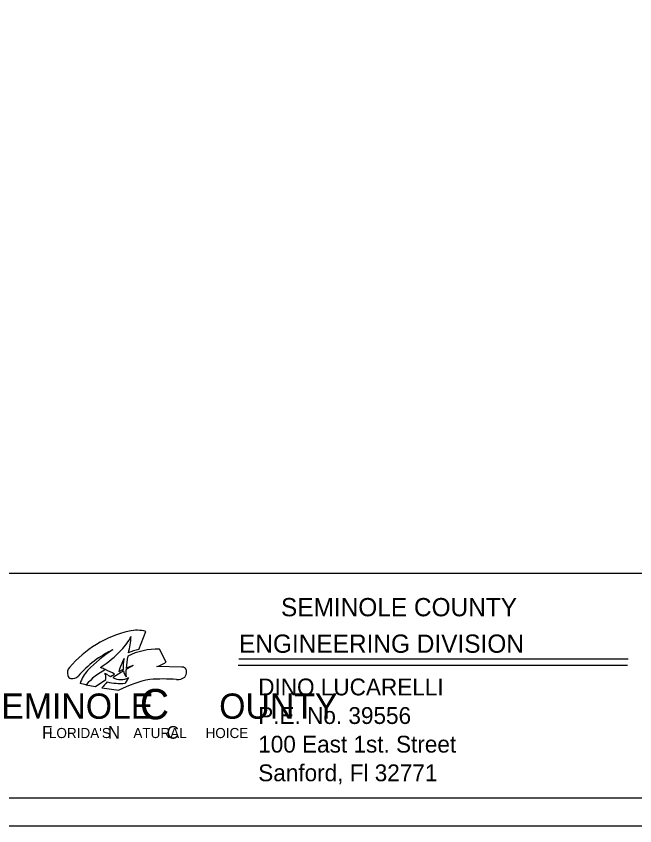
# Model space of a CAD drawing. Extents: x 539344 to 540004, y 1574686 to 1575110.
# Drawn here: x 539600.9 to 539689, y 1574686.5 to 1574801.8 of the extents above; entities that cross this region are included whole.
import ezdxf

# ---------------------------------------------------------------- set-up
doc = ezdxf.new("R2010")
doc.units = 0
for name, color, linetype in [('Logo_dp', 7, 'Continuous'), ('PlotBorder_dp', 7, 'Continuous'), ('SheetBorder_dp', 7, 'Continuous'), ('TextMisc', 7, 'Continuous')]:
    doc.layers.add(name, color=color, linetype=linetype)

msp = doc.modelspace()

# ---------------------------------------------------------------- linework, layer by layer
at = {"layer": 'Logo_dp'}
for p, q in [((539618.37, 1574711.59), (539619.39, 1574714.15)), ((539622.26, 1574709.78), (539621.31, 1574711.62)), ((539624.5, 1574709.07), (539620.95, 1574709.15)), ((539614.36, 1574707.7), (539614.93, 1574708.05)), ((539612.21, 1574706.28), (539613.68, 1574707.27)), ((539613.68, 1574707.27), (539613.68, 1574707.85)), ((539616.92, 1574707.57), (539616.42, 1574706.76)), ((539610.85, 1574706.54), (539612.21, 1574706.28)), ((539613.13, 1574706.1), (539615.54, 1574705.76))]:
    msp.add_line(p, q, dxfattribs=at)
for points in [[(539617.02, 1574714.19), (539617.02, 1574714.19)], [(539611.09, 1574708.58), (539611.09, 1574708.58)]]:
    msp.add_lwpolyline(points, dxfattribs=at)
for centre, radius, start, end in [((539620.59, 1574698.7), 15.89, 102.9903, 139.6059), ((539618.13, 1574709.35), 4.96, 75.3253, 102.9903), ((539610.89, 1574716.45), 7.05, 315.4846, 334.5843), ((539608.31, 1574713.66), 8.96, 343.2724, 358.4983), ((539620.79, 1574698.34), 14.53, 114.9659, 139.5324), ((539624.77, 1574695.63), 18.84, 122.4911, 136.5671), ((539601.1, 1574726.09), 20.79, 304.6341, 315.4846), ((539621.11, 1574701.89), 9.74, 88.8097, 116.3253), ((539619.98, 1574704.41), 7.35, 102.6743, 114.927), ((539622.26, 1574706.8), 6.91, 149.8559, 166.6084), ((539620.31, 1574709.17), 4.17, 164.7271, 186.2913), ((539629.12, 1574708.11), 12.58, 168.5397, 176.4368), ((539629.51, 1574685.9), 26.24, 117.0216, 119.5789), ((539621.65, 1574696.98), 12.96, 108.2919, 113.1245), ((539619.53, 1574713.79), 4.86, 286.9862, 304.2368), ((539624.53, 1574708.43), 0.643, 0.9885, 92.5741), ((539609.42, 1574708.21), 1.22, 139.6059, 196.4516), ((539614.46, 1574705.39), 4.64, 136.5671, 163.5792), ((539618, 1574700.23), 9.53, 117.2749, 138.5612), ((539618, 1574700.23), 9.53, 117.2749, 138.5612), ((539611.87, 1574705.19), 3.93, 63.4009, 74.6531), ((539613.08, 1574707.75), 0.608, 9.3089, 39.4038), ((539613.28, 1574707.02), 1.15, 52.8844, 76.2699), ((539607.58, 1574695.02), 14.96, 60.5981, 66.1485), ((539615.16, 1574709.45), 1.93, 231.8585, 245.4301), ((539629.51, 1574685.9), 26.24, 120.5054, 124.3665), ((539621.65, 1574696.98), 12.96, 115.0847, 118.1751), ((539617.71, 1574708.72), 1.54, 187.6078, 223.6575), ((539629.12, 1574708.11), 12.58, 177.2074, 179.7242), ((539618.24, 1574708.11), 1.71, 177.7479, 195.3391), ((539624.1, 1574708.33), 1.07, 319.3898, 5.6197), ((539608.82, 1574708.03), 0.599, 196.4516, 259.2243), ((539608.92, 1574708.55), 1.12, 259.2243, 316.3038), ((539624.04, 1574697.34), 13.99, 136.6419, 141.2542), ((539615.74, 1574714.82), 8.09, 256.604, 274.8219), ((539615.8, 1574709.7), 2.41, 242.5498, 297.6527), ((539622.82, 1574691.88), 15.68, 100.5294, 117.6775), ((539621.85, 1574686.34), 21.03, 84.8254, 95.1746), ((539623.93, 1574708.81), 1.53, 262.9671, 309.9257), ((539606.9, 1574688.08), 18.88, 77.906, 80.5112)]:
    msp.add_arc(centre, radius, start, end, dxfattribs=at)
at = {"layer": 'PlotBorder_dp'}
msp.add_lwpolyline([(539343.95, 1574686.45), (540003.95, 1574686.45), (540003.95, 1575110.45), (539343.95, 1575110.45)], close=True, dxfattribs=at)
at = {"layer": 'SheetBorder_dp'}
for p, q in [((539365.95, 1574722.45), (539981.95, 1574722.45)), ((539365.95, 1574690.45), (539981.95, 1574690.45))]:
    msp.add_line(p, q, dxfattribs=at)
at = {"layer": 'TextMisc'}
for p, q in [((539632.6, 1574710.24), (539688.06, 1574710.24)), ((539632.52, 1574709.34), (539687.98, 1574709.34))]:
    msp.add_line(p, q, dxfattribs=at)

# ---------------------------------------------------------------- texts
at = {"layer": 'Logo_dp'}
for s, height, p in [('C', 4.32, (539618.52, 1574701.62)), ('EMINOLE       OUNTY', 3.6, (539598.79, 1574701.7)), ('F', 1.8, (539604.6, 1574698.86)), ("LORIDA'S      ATURAL     HOICE", 1.44, (539605.57, 1574698.95)), ('N', 1.8, (539613.97, 1574698.86)), ('C', 1.8, (539622.34, 1574698.86))]:
    msp.add_text(s, height=height, dxfattribs=at).set_placement(p)
at = {"layer": 'TextMisc'}
for s, height, p in [('SEMINOLE COUNTY', 2.6, (539638.62, 1574716.3)), ('ENGINEERING DIVISION', 2.6, (539632.65, 1574711.1)), ('DINO LUCARELLI', 2.4, (539635.38, 1574705.03)), ('P.E. No. 39556', 2.4, (539635.38, 1574700.96)), ('100 East 1st. Street', 2.4, (539635.38, 1574696.88)), ('Sanford, Fl 32771', 2.4, (539635.38, 1574692.8))]:
    msp.add_text(s, height=height, dxfattribs=at).set_placement(p)

doc.saveas('drawing.dxf')
